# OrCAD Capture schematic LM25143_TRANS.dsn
size Custom; title: LM25143 Automotive 3.5-V to 42-V Dual Synchronous Buck; rev: 1.0; note: Datasheet: SNVSC11     EVM: NA; note: Synchronous Step Down Converter
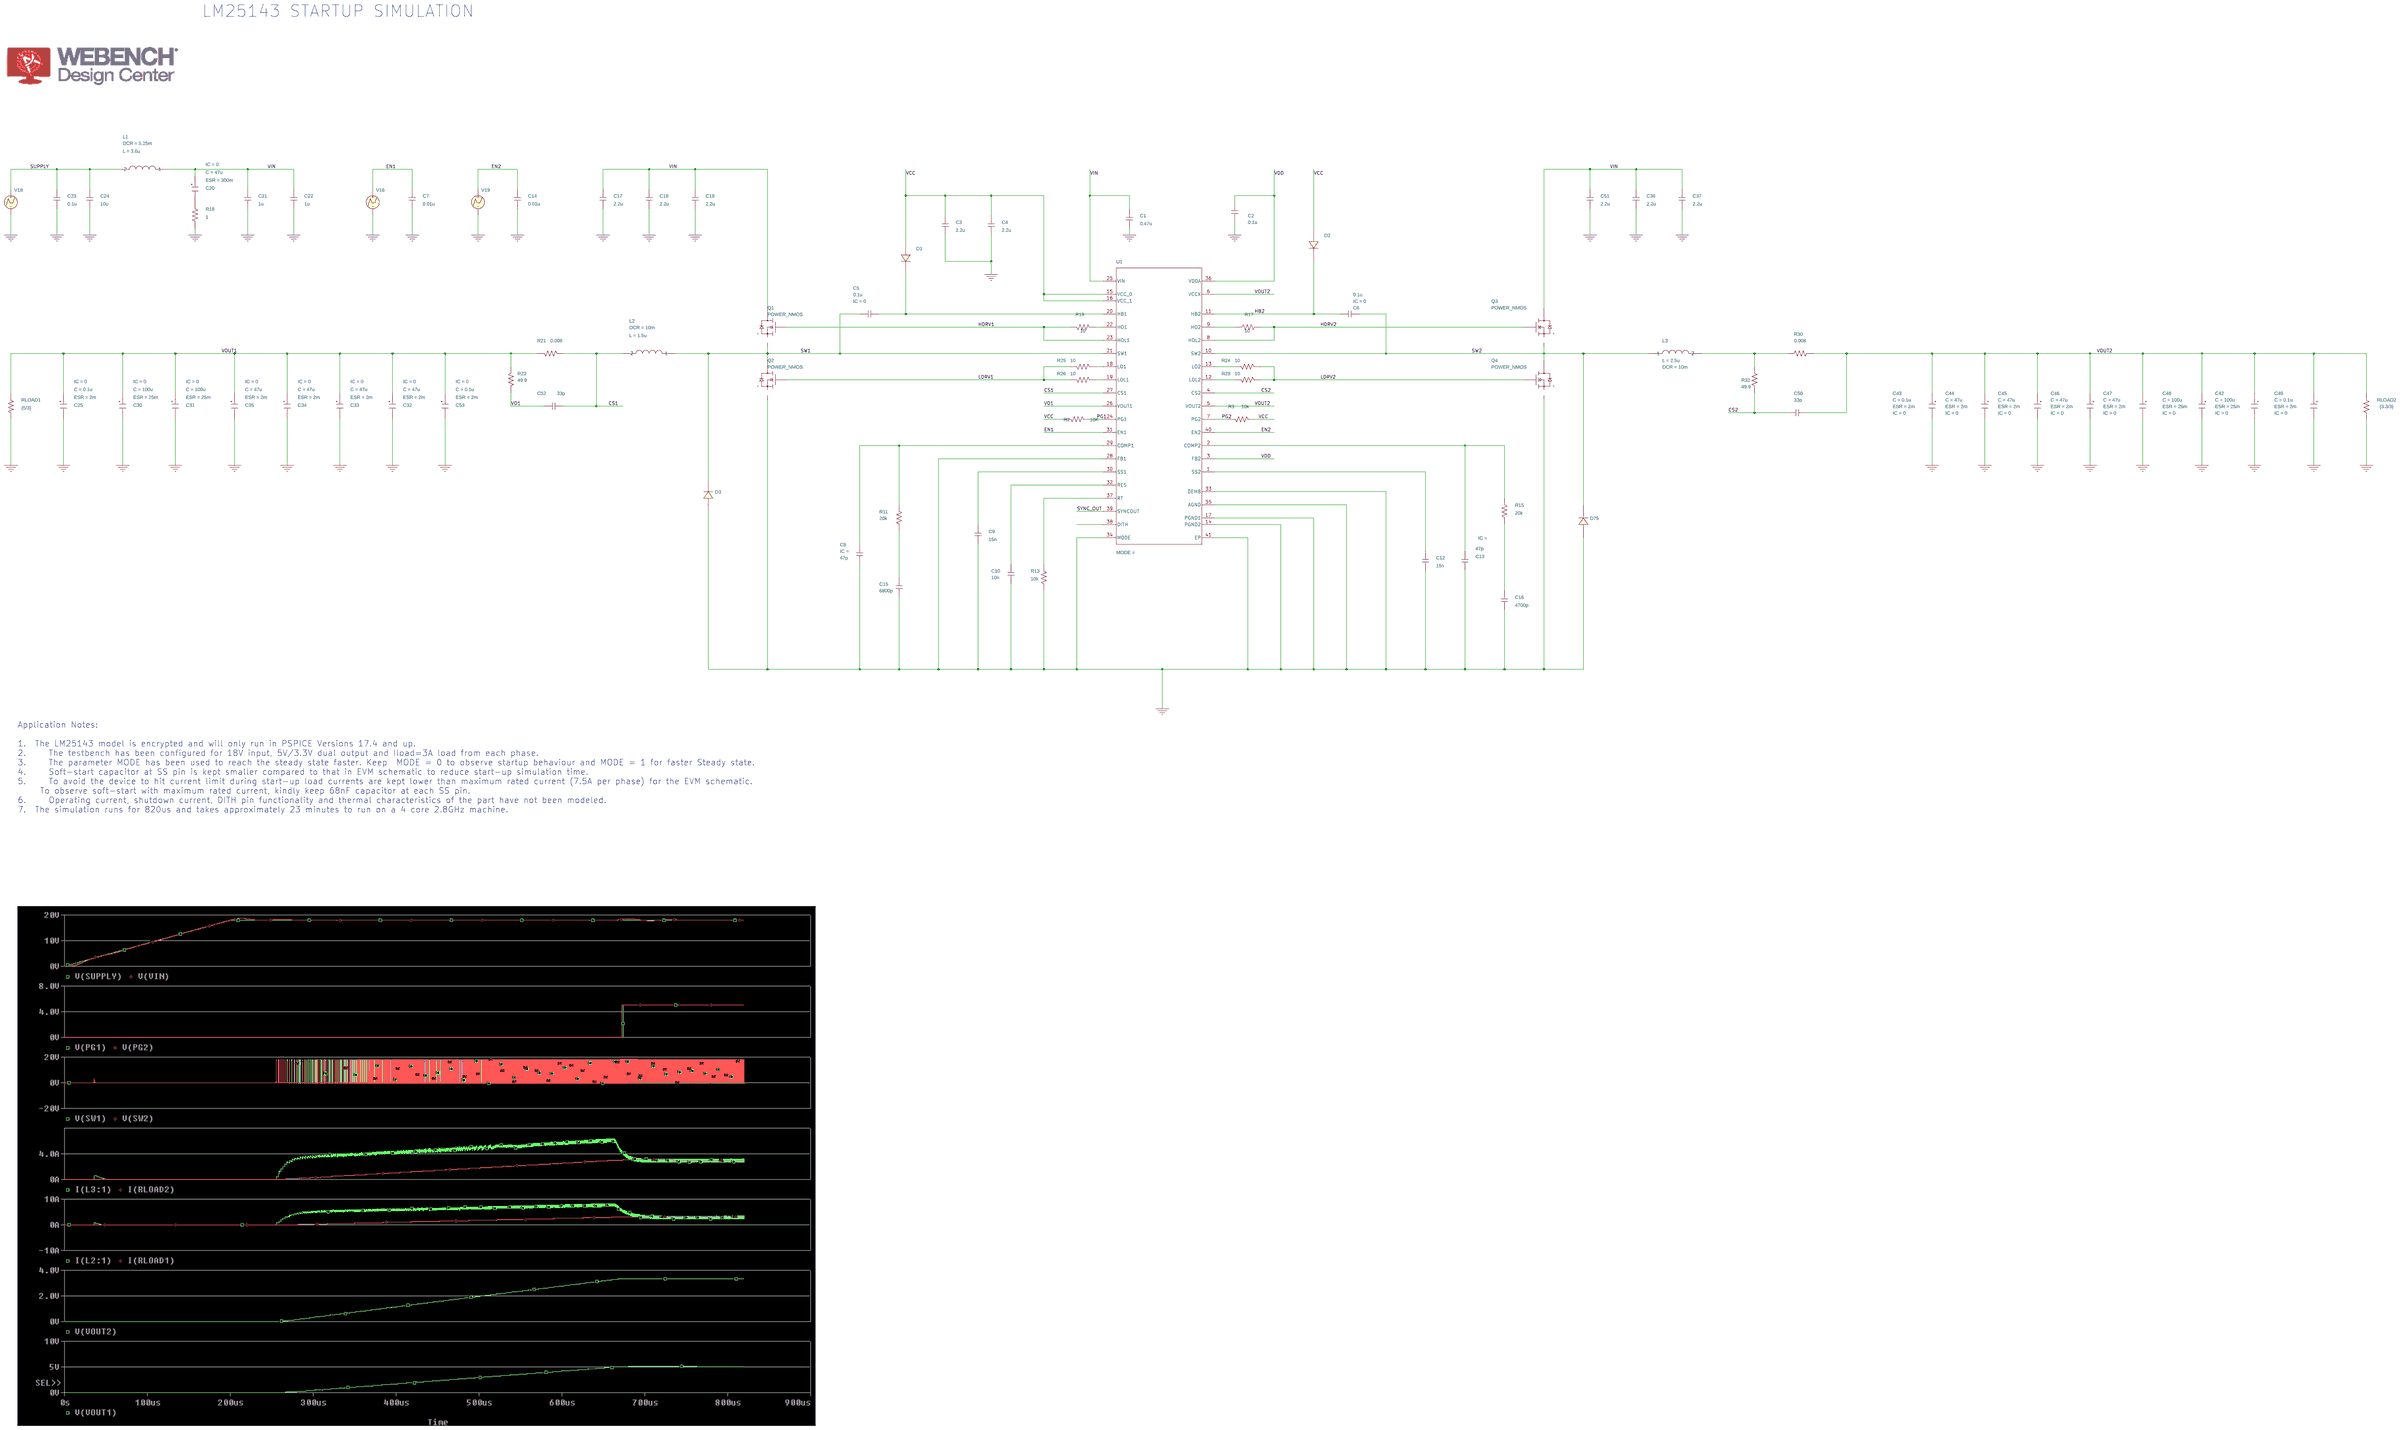
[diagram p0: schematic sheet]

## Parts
C1  0.47u  [RAD/CK05]
C2  0.1u  [RAD/CK05]
C3  2.2u  [RAD/CK05]
C4  2.2u  [RAD/CK05]
C5  0.1u  [RAD/CK05]
C6  0.1u  [RAD/CK05]
C7  0.01u  [RAD/CK05]
C8  47p  [RAD/CK05]
C9  15n  [RAD/CK05]
C10  10n  [RAD/CK05]
C12  15n  [RAD/CK05]
C13  47p  [RAD/CK05]
C14  0.01u  [RAD/CK05]
C15  6800p  [RAD/CK05]
C16  4700p  [RAD/CK05]
C17  2.2u  [RAD/CK05]
C18  2.2u  [RAD/CK05]
C19  2.2u  [RAD/CK05]
C20  CESR
C21  1u  [RAD/CK05]
C22  1u  [RAD/CK05]
C23  0.1u  [RAD/CK05]
C24  10u  [RAD/CK05]
C25  CESR
C30  CESR
C31  CESR
C32  CESR
C33  CESR
C34  CESR
C35  CESR
C36  2.2u  [RAD/CK05]
C37  2.2u  [RAD/CK05]
C42  CESR
C43  CESR
C44  CESR
C45  CESR
C46  CESR
C47  CESR
C48  CESR
C49  CESR
C50  33p  [RAD/CK05]
C51  2.2u  [RAD/CK05]
C52  33p  [RAD/CK05]
C53  CESR
D1  D_D1
D2  D_D1
D3  D_D1
D75  D_D1
L1  LDCR
L2  LDCR
L3  LDCR
Q1  POWER_NMOS
Q2  POWER_NMOS
Q3  POWER_NMOS
Q4  POWER_NMOS
R2  10K  [AX/RC05]
R3  10k  [AX/RC05]
R11  20k  [AX/RC05]
R13  10k  [AX/RC05]
R15  20k  [AX/RC05]
R17  10  [AX/RC05]
R18  1  [AX/RC05]
R19  10  [AX/RC05]
R21  0.008  [AX/RC05]
R23  49.9  [AX/RC05]
R24  10  [AX/RC05]
R25  10  [AX/RC05]
R26  10  [AX/RC05]
R28  10  [AX/RC05]
R30  0.008  [AX/RC05]
R32  49.9  [AX/RC05]
RLOAD1  {5/3}  [AX/RC05]
RLOAD2  {3.3/3}  [AX/RC05]
U1  Value  [RHA0040P-IPC_A]
V16  VPWL
V18  VPWL
V19  VPWL

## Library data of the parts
C1 C3 C4 C7-C10 C12-C19 C21-C24 C36 C37 C50-C52 = C
C2 = C: IC: 3.4
C5 C6 = C: IC: 0
C20 = CESR_0: C: 47u; ESR: 300m; IC: 0; PSpiceTemplate: X^@REFDES %IN %OUT @MODEL PARAMS:  ?C|C=@C||C=100u|  ?ESR|ESR=@ESR||ESR=0.01| ?X|X=@X||X=2|  ?IC|IC=@IC||IC=2|; X: 1
C25 C43 C49 C53 = CESR_0: C: 0.1u; ESR: 2m; IC: 0; PSpiceTemplate: X^@REFDES %IN %OUT @MODEL PARAMS:  ?C|C=@C||C=100u|  ?ESR|ESR=@ESR||ESR=0.01| ?X|X=@X||X=2|  ?IC|IC=@IC||IC=2|; X: 1
C30 C31 C42 C48 = CESR_0: C: 100u; ESR: 25m; IC: 0; PSpiceTemplate: X^@REFDES %IN %OUT @MODEL PARAMS:  ?C|C=@C||C=100u|  ?ESR|ESR=@ESR||ESR=0.01| ?X|X=@X||X=2|  ?IC|IC=@IC||IC=2|; X: 1
C32-C35 C44-C47 = CESR_0: C: 47u; ESR: 2m; IC: 0; PSpiceTemplate: X^@REFDES %IN %OUT @MODEL PARAMS:  ?C|C=@C||C=100u|  ?ESR|ESR=@ESR||ESR=0.01| ?X|X=@X||X=2|  ?IC|IC=@IC||IC=2|; X: 1
D1-D3 D75 = D_D1
L1 = LDCR_1: DCR: 5.25m; L: 3.6u
L2 = LDCR_2: DCR: 10m; L: 1.5u
L3 = LDCR: DCR: 10m; L: 2.5u
Q1-Q4 = CSD17579Q3A
R2 R3 R11 R13 R15 R17-R19 R21 R23-R26 R28 R30 R32 RLOAD1 RLOAD2 = R
U1 = LM25143RHA_TRANS
V16 V19 = VPWL: PSpiceTemplate: V^@REFDES %+ %- ?DC|DC @DC| ?AC|AC @AC|\n+PWL @T1 @V1 @T2 @V2 #T3/@T3 @V3/ #T4/@T4 @V4/ #T5/@T5 @V5/ #T6/@T6 @V6/ #T7/@T7 @V7/ #T8/@T8 @V8/ #T9/@T9 @V9/ #T10/@T10 @V10/; T1: 0; T2: 10u; V1: 0; V2: 5
V18 = VPWL: PSpiceTemplate: V^@REFDES %+ %- ?DC|DC @DC| ?AC|AC @AC|\n+PWL @T1 @V1 @T2 @V2 #T3/@T3 @V3/ #T4/@T4 @V4/ #T5/@T5 @V5/ #T6/@T6 @V6/ #T7/@T7 @V7/ #T8/@T8 @V8/ #T9/@T9 @V9/ #T10/@T10 @V10/; T1: 0; T2: 200u; T3: 300u; V1: 0; V2: 18; V3: 18

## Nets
VCC: C3.1 C4.1 D1.2(A) D2.2(A) R2.1 R3.2 U1.15(VCC_0) U1.16(VCC_1)
VDD: C2.1 U1.3(FB2) U1.36(VDDA)
VIN: C1.2 C17.1 C18.1 C19.1 C20.1(IN) C21.1 C22.1 C36.1 C37.1 C51.1 L1.1 Q1.3(drain) Q3.3(drain) U1.25(VIN)
0: C1.1 C2.2 C3.2 C4.2 C7.1 C8.2 C9.2 C10.1 C12.2 C13.2 C14.1 C15.1 C16.1 C17.2 C18.2 C19.2 C21.2 C22.2 C23.1 C24.1 C25.2(OUT) C30.2(OUT) C31.2(OUT) C32.2(OUT) C33.2(OUT) C34.2(OUT) C35.2(OUT) C36.2 C37.2 C42.2(OUT) C43.2(OUT) C44.2(OUT) C45.2(OUT) C46.2(OUT) C47.2(OUT) C48.2(OUT) C49.2(OUT) C51.2 C53.2(OUT) D3.2(A) D75.2(A) Q2.1(source) Q4.1(source) R13.2 R18.1 RLOAD1.2 RLOAD2.2 U1.14(PGND2) U1.17(PGND1) U1.28(FB1) U1.33(DEMB) U1.34(MODE) U1.35(AGND) U1.41(EP) V16.2(-) V18.2(-) V19.2(-)
CS1: C52.2 L2.2 R21.2 U1.27(CS1)
CS2: C50.2 R32.1 U1.4(CS2)
EN1: C7.2 U1.31(EN1) V16.1(+)
EN2: C14.2 U1.40(EN2) V19.1(+)
HB2: C6.1 D2.1(C) U1.11(HB2)
HDRV1: Q1.2(gate) R19.2 U1.23(HOL1)
HDRV2: Q3.2(gate) R17.2 U1.8(HOL2)
LDRV1: Q2.2(gate) R25.2 R26.2
LDRV2: Q4.2(gate) R24.1 R28.1
PG1: R2.2 U1.24(PG1)
PG2: R3.1 U1.7(PG2)
SUPPLY: C23.2 C24.2 L1.2 V18.1(+)
SW1: C5.2 D3.1(C) L2.1 Q1.1(source) Q2.3(drain) U1.21(SW1)
SW2: C6.2 D75.1(C) L3.1 Q3.1(source) Q4.3(drain) U1.10(SW2)
SYNC_OUT: U1.39(SYNCOUT)
VO1: C52.1 R23.1 U1.26(VOUT1)
VOUT1: C25.1(IN) C30.1(IN) C31.1(IN) C32.1(IN) C33.1(IN) C34.1(IN) C35.1(IN) C53.1(IN) R21.1 R23.2 RLOAD1.1
VOUT2: C42.1(IN) C43.1(IN) C44.1(IN) C45.1(IN) C46.1(IN) C47.1(IN) C48.1(IN) C49.1(IN) C50.1 R30.1 RLOAD2.1 U1.5(VOUT2) U1.6(VCCX)
N29384: C12.1 U1.1(SS2)
N34337: C16.2 R15.1
N34343: C13.1 R15.2 U1.2(COMP2)
N86263: R13.1 U1.37(RT)
N88026: C10.2 U1.32(RES)
N91194: C9.1 U1.30(SS1)
N94411: C15.2 R11.1
N94417: C8.1 R11.2 U1.29(COMP1)
N119731: R19.1 U1.22(HO1)
N156761: C5.1 D1.1(C) U1.20(HB1)
N16785518: L3.2 R30.2 R32.2
N16806015: C20.2(OUT) R18.2
N16807402: R28.2 U1.12(LOL2)
N16807406: R17.1 U1.9(HO2)
N16807408: R24.2 U1.13(LO2)
N16818691: R26.1 U1.19(LOL1)
N16820302: R25.1 U1.18(LO1)

Not connected (* = marked no-connect by the designer): U1 38(DITH)

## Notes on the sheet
- LM25143 STARTUP SIMULATION
- Application Notes:
  1.  The LM25143 model is encrypted and will only run in PSPICE Versions 17.4 and up.
  2.	  The testbench has been configured for 18V input, 5V/3.3V dual output and Iload=3A load from each phase.
  3.	  The parameter MODE has been used to reach the steady state faster. Keep  MODE = 0 to observe startup behaviour and MODE = 1 for faster Steady state.
  4.	  Soft-start capacitor at SS pin is kept smaller compared to that in EVM schematic to reduce start-up simulation time.
  5.	  To avoid the device to hit current limit during start-up load currents are kept lower than maximum rated current (7.5A per phase) for the EVM schematic.
       To observe soft-start with maximum rated current, kindly keep 68nF capacitor at each SS pin.
  6.	  Operating current, shutdown current, DITH pin functionality and thermal characteristics of the part have not been modeled.
  7.  The simulation runs for 820us and takes approximately 23 minutes to run on a 4 core 2.8GHz machine.
